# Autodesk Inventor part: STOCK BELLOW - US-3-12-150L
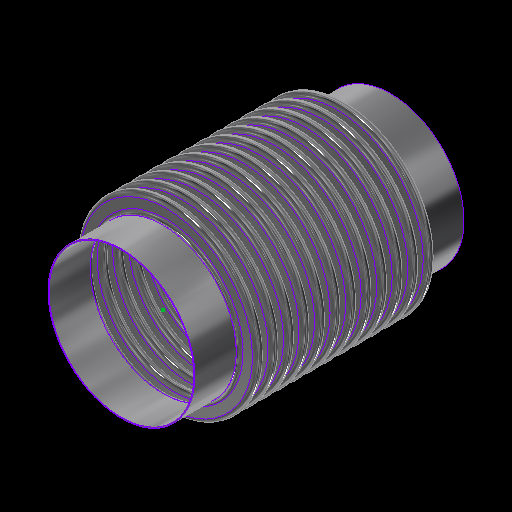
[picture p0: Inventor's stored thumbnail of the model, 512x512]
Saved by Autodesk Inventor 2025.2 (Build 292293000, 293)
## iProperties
Category: 24 GA (0.024 THICK)
RuleStatus: InUse
Created: 2024-01
Part Number: STOCK BELLOW - US-3-12-150L
Project: =STOCK BELLOWS: <Stock Number><SFILL>
Material: ASTM A240-304
Description: =STOCK BELLOWS: <Stock Number>, <SID_> I.D., <SOD_> O.D., <SPLY_> PLY, <Category>, <SNET_CONS> CONS.<PITCH_><STANGENT_> TANGENT<SFILL>
Document SubType Name: Sheet Metal
Designer: GS
Stock Number: U.S-3-12-150L
Surface Area: 2289.96 cm^2
Volume: 69.4846 cm^3
Sheet Metal Rule: Default
Appearance: STAINLESS STEEL
Mass: 559.857 g
Density: 8.05729 g/cm^3
THK: 0.036
ID: 3.500
OD: 4.250
CONS_: 2
PITCH: 0.500
TANGENT: 0.500
BELLOWS_UPSET: 0.000
d79: 1.000
d82: 1.000
d83: 26.000
d84: 24.000
d174: 8
d214: 8
STHK_: 0.024
SID_: 3.500
SOD_: 4.375
SPITCH_: 0.375
STANGENT__: 1.000
SBELLOWS_UPSET_: 0.000
SDIFF_TAN: 1.000
d252: 2
d275: 2
d287: 0.050
d289: 0.500
d290: 0.000
SOD_NECK: 3 9/16
PLY: 1
PSET: 4.178
PBAR: 1.035
COUNTER: 1.500
NET_TUBE: 3.071
CONS: 2
S_CONS: 0
NET_CONS: 2
ID_M: 88.90 mm
OD_M: 107.95 mm
THK_M: 0.91 mm
ID_U: 3.500 in
OD_U: 4.250 in
THK_U: 0.036 in
TANGENT2: 0.500
TAN_TO_TAN: 1.000 in
d80: 2.571
d81: 10
SID: 2.375
SCONS_: 12
SPITCH: 0.250
STANGENT_: 1.000
SBELLOWS_UPSET: 0.000
SNET_CONS: 12
SS_CONS: 0
SCONS: 8
d190: 8
d191: 1
d192: 1
d193: 8
d194: 0
SIZE: 3.00
PRESSURE: 150
d230: 8
STANGENT: 4.000
SPLY_: 1
d233: 8
d234: 0
d263: 2
d265: 1
d268: 2
d269: 0
d286: 2
d288: 1
d291: 2
d292: 0
SREROLL: 0.750
BLETP: 1.000 ul
PRES_Copy: 85
MATTABLE: 20 GA (0.036 THICK)
PART_NUMBER: U.S-3-12-150L
PITCH_: =, <SPITCH_> PITCH,
CFILL: .
SFILL: .
MESH: ,
COMP: 0.82
EXT: 0.41
LAT: 0.31
ANG: 573
ASR: 974
LSR: 1007
ANSR: 30
PRES: 150
COMPM: 8.2
EXTM: 4.1
LATM: 3.10
ASRM: 170.577
PRESM: 10.342
LSRM: 176.356
ANSRM: 5.254
TEMPMIN: 20
TEMPMAX: 800
TEMPMINM: -7
TEMPMAXM: 427
WEIGHTM: 0.560
WEIGHT: 1.234
Author: GS
Keywords: 20 GA (0.036 THICK)
Comments: =STOCK BELLOW - <STOCK NUMBER>
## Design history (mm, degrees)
sketch "Sketch2"
  geometry: L1 (0, -177.245)-(0, 562.856) reference; L2 (45.364, 0)-(44.45, 0); L3 (48.082, -2.718)-(50.343, -2.718); L4 (48.082, -3.632)-(50.343, -3.632); L5 (50.343, -9.982)-(48.082, -9.982); L6 (50.343, -9.068)-(48.082, -9.068); L7 (45.364, -12.7)-(44.45, -12.7); L8 (48.082, 0)-(48.082, -12.7); L9 (50.343, -6.35)-(53.975, -6.35); L10 (44.45, 0)-(44.45, -12.7); L11 (20.376, 102.841)-(20.376, 101.926); L12 (58.262, 457.127)-(58.262, 349.177); L13 (58.262, 444.427)-(58.262, 336.477); L14 (93.133, -58.817)-(93.133, -71.517); L15 (118.746, -66.401)-(118.746, -66.401); L16 (50.343, -9.068)-(50.343, -9.982); L17 (48.082, -9.068)-(48.082, -9.982); L18 (48.082, -9.525)-(50.343, -9.525); L19 (53.975, 0)-(53.975, -12.7); L20 (-50.343, -9.068)-(-50.343, -9.982); L21 (-50.343, -2.718)-(-48.082, -2.718); L22 (-50.343, -3.632)-(-48.082, -3.632); L23 (-48.082, -9.068)-(-50.343, -9.068); L24 (-50.343, -9.525)-(-48.082, -9.525); L25 (-48.082, -9.982)-(-50.343, -9.982); L26 (-48.082, -9.068)-(-48.082, -9.982); L27 (-44.45, 0.653)-(-44.45, -12.047); L28 (-48.082, -6.35)-(-44.45, -6.35); L29 (-50.343, 0.653)-(-50.343, -12.7); L30 (-53.061, 0)-(-53.975, 0); L31 (-53.975, 0)-(-53.975, -12.7); L32 (-53.061, -12.7)-(-53.975, -12.7); A1 r 2.718 centre (48.082, 0) between (45.364, 0) and (48.082, -2.718); A2 r 3.632 centre (48.082, 0) between (44.45, 0) and (48.082, -3.632); A3 r 3.632 centre (50.343, -6.35) between (50.343, -9.982) and (50.343, -2.718); A4 r 2.718 centre (50.343, -6.35) between (50.343, -9.068) and (50.343, -3.632); A5 r 2.718 centre (48.082, -12.7) between (48.082, -9.982) and (45.364, -12.7); A6 r 3.632 centre (48.082, -12.7) between (48.082, -9.068) and (44.45, -12.7); A7 r 3.175 centre (50.343, -6.35) between (50.343, -9.525) and (53.518, -6.35); A8 r 3.175 centre (48.082, -12.7) between (48.082, -9.525) and (44.907, -12.7); A9 r 2.718 centre (-50.343, -12.7) between (-50.343, -9.982) and (-53.061, -12.7); A10 r 2.718 centre (-48.082, -6.35) between (-48.082, -9.068) and (-48.082, -3.632); A11 r 3.175 centre (-48.082, -6.35) between (-48.082, -9.525) and (-44.907, -6.35); A12 r 3.632 centre (-48.082, -6.35) between (-48.082, -9.982) and (-48.082, -2.718); A13 r 3.175 centre (-50.343, -12.7) between (-50.343, -9.525) and (-53.518, -12.7); A14 r 3.632 centre (-50.343, -12.7) between (-50.343, -9.068) and (-53.975, -12.7); A15 r 2.718 centre (-50.343, 0) between (-53.061, 0) and (-50.343, -2.718); A16 r 3.632 centre (-50.343, 0) between (-53.975, 0) and (-50.343, -3.632); 10 further points
  constraints: 62 end point, 38 point on circle, 20 tangent, 16 centre point, 12 parallel, 9 midpoint, 7 vertical, 6 coincident, 6 concentric, 6 point on line, 4 equal radius, 4 perpendicular, 3 horizontal, 1 collinear, 1 horizontal alignment, 10 other
  dimensions: "THK" = 0.9144 distance of L11.start L11.end; "ID" = 88.9 distance of L11.end point (20.376, 13.026); "OD" = 107.95 distance of L12.start L12.end; "PITCH" = 12.7 distance of L12.start L13.start; "TANGENT" = 12.7 distance of L14.start L14.end; "BELLOWS_UPSET" = 0 distance of L15.start L15.end; "d43" = 88.9 diameter of L10 L1 (= ID); "d44" = 107.95 diameter of L9.end L1 (= OD); "d45" = 0.9144 distance between parallel lines of L5 L6 (computed from THK, PLY); "d46" = 3.6322 radius of A3 (computed from PITCH, THK, PLY); "UPSET_PITCH" = 12.7 distance of L2.end L7.end (derived); "SIDEWALL_ANGLE" = 360 deg dimension on L3 L9 (derived); "CON_GAP" = 5.4356 distance of point (48.082, -9.068) point (48.082, -3.632) (derived); "TAN1" = 4.98728 dimension on A8 (derived); "TAN2" = 4.98728 dimension on A7 (derived); "LEG1" = 2.2606 distance of L18.start L18.end (derived); "d278" = 0.9144 distance between parallel lines of L25 L23 (derived); "d279" = 3.6322 radius of A12 (derived); "d280" = 12.7 distance of L30.end L31.end (derived); "d281" = 360 deg dimension on L21 L28 (derived); "d282" = 5.4356 distance of point (-50.343, -9.068) point (-50.343, -3.632) (derived); "d283" = 4.98728 dimension on A13 (derived); "d284" = 4.98728 dimension on A11 (derived); "d285" = 2.2606 distance of L24.start L24.end (derived); "d293" = 88.9 diameter of L27 L1 (derived); "d294" = 107.95 diameter of L31 L1 (derived)
  node "Sketch Rectangular Pattern1" dims "d31" = 25.4, "ID" = 88.9
  node "Sketch Rectangular Pattern2" dims "d39" = 25.4, "PITCH" = 12.7
revolve "CONS" stored, may be unused: angle "d48" = 90 deg
node "BELLOW MIDPLANE"
pattern_linear "Rectangular Pattern2" dims "d52" = 12.7 (= UPSET_PITCH)
sketch "Sketch5"
  geometry: C1 r 45.364 at (0, 0) reference; C2 r 44.45 at (0, 0) reference
extrude "TANGENT" new body sketch "Sketch5" distance "d53" = 12.7 (= TANGENT); taper "d54" = 0 deg
revolve "SAMETAN" stored, may be unused: angle "d65" = 90 deg
revolve "DIFFTAN" stored, may be unused: angle "d70" = 90 deg
sketch "Sketch9"
  geometry: L1 (53.319, 0)-(-53.319, 0) reference; L2 (0, -17.78)-(0, 17.78) reference; L3 (38.085, 0)-(-38.085, 0); L4 (38.085, -11.906)-(38.085, 11.906); L5 (25.385, -11.906)-(25.385, 11.906); L6 (13.15, 11.906)-(13.15, -11.906); L7 (-25.385, -11.906)-(-25.385, 11.906); L8 (-38.085, -11.906)-(-38.085, 11.906); L9 (37.291, -11.906)-(37.291, 11.906); L10 (38.085, -11.906)-(37.291, -11.906); L11 (38.085, 11.906)-(37.291, 11.906); L12 (13.546, 11.906)-(12.753, 11.906); L13 (12.753, 11.906)-(12.753, -11.906); L14 (12.753, -11.906)-(13.546, -11.906); L15 (13.546, -11.906)-(13.546, 11.906); L16 (-13.546, 11.906)-(-13.546, -11.906); L17 (-13.15, 11.906)-(-13.15, -11.906); L18 (-13.546, -11.906)-(-12.753, -11.906); L19 (-12.753, -11.906)-(-12.753, 11.906); L20 (-12.753, 11.906)-(-13.546, 11.906); L21 (-38.085, -11.906)-(-37.291, -11.906); L22 (-37.291, -11.906)-(-37.291, 11.906); L23 (-37.291, 11.906)-(-38.085, 11.906); L24 (-38.085, 11.906)-(-38.085, -11.906); L25 (38.085, -0.397)-(-38.085, -0.397); L26 (-38.085, -0.397)-(-38.085, 0.397); L27 (-38.085, 0.397)-(38.085, 0.397); L28 (38.085, 0.397)-(38.085, -0.397); L29 (-38.085, 11.906)-(38.085, 11.906); L30 (38.085, 11.906)-(38.085, 12.7); L31 (38.085, 12.7)-(-38.085, 12.7); L32 (-38.085, 12.7)-(-38.085, 11.906); L33 (38.085, -11.906)-(-38.085, -11.906); L34 (-38.085, -11.906)-(-38.085, -12.7); L35 (-38.085, -12.7)-(38.085, -12.7); L36 (38.085, -12.7)-(38.085, -11.906); 30 further points
  constraints: 68 end point, 13 midpoint, 13 parallel, 8 horizontal, 7 perpendicular, 6 equal length, 3 point on line, 2 vertical, 14 other
  dimensions: "d115" = 23.8125 distance of L4.start L4.end (derived); "d116" = 12.7 distance between parallel lines of L4 L5 (derived); "d117" = 12.23516 distance between parallel lines of L5 L6 (derived); "d125" = 38.53427 distance between parallel lines of L7 L6 (derived); "d127" = 12.7 distance between parallel lines of L8 L7 (derived); "d128" = 24.93516 distance between parallel lines of L6 L4 (derived); "d130" = 76.16943 distance between parallel lines of L8 L4 (derived); "RULER_THK" = 0.79375 distance between parallel lines of L4 L9; "d135" = 0.79375 distance of L13.end L14.end (derived); "d138" = 26.29911 distance of L13.end L16.end (derived); "d143" = 0.79375 distance of L22.end L8.end (derived); "d144" = 0.79375 distance between parallel lines of L27 L25 (derived)
extrude "RULER" join sketch "Sketch9" distance "d149" = 0.79375 (derived); taper "d150" = 0 deg
extrude "BARS" join sketch "Sketch9" distance "d151" = 0.79375 (derived); taper "d152" = 0 deg
pattern_linear "Rectangular Pattern4" dims "d155" = 26.29911 (derived)
sketch "Sketch13"
  geometry: L1 (93.149, -52.467)-(93.149, -77.867); L2 (45.06, 0)-(44.45, 0); L3 (45.06, -9.525)-(44.45, -9.525); L4 (52.876, -7.449)-(47.136, -7.449); L5 (52.876, -6.839)-(47.136, -6.839); L6 (52.876, -4.762)-(55.562, -4.762); L7 (47.136, -2.076)-(52.876, -2.076); L8 (47.136, 0)-(47.136, -9.525); L9 (44.45, 0)-(44.45, -9.525); L10 (58.254, -385.306)-(58.254, -496.431); L11 (58.254, -394.831)-(58.254, -505.956); L12 (58.254, -413.881)-(58.254, -525.006); L13 (58.254, -423.406)-(58.254, -534.531); L14 (58.254, -432.931)-(58.254, -544.056); L15 (58.254, -442.456)-(58.254, -553.581); L16 (58.254, -451.981)-(58.254, -563.106); L17 (58.254, -404.356)-(58.254, -515.481); L18 (20.376, 102.536)-(20.376, 101.926); L19 (47.136, -2.686)-(52.876, -2.686); L20 (0, -696.234)-(0, 235.664) reference; L21 (-23.752, 0)-(142.514, 0) reference; A1 r 2.076 centre (47.136, 0) between (45.06, 0) and (47.136, -2.076); A2 r 2.076 centre (47.136, -9.525) between (47.136, -7.449) and (45.06, -9.525); A3 r 2.686 centre (47.136, -9.525) between (47.136, -6.839) and (44.45, -9.525); A4 r 2.076 centre (52.876, -4.762) between (52.876, -6.839) and (52.876, -2.686); A5 r 2.686 centre (52.876, -4.762) between (52.876, -7.449) and (52.876, -2.076); A6 r 2.686 centre (47.136, 0) between (44.45, 0) and (47.136, -2.686); 6 further points; 1 other entity
  constraints: 38 end point, 15 point on circle, 9 tangent, 6 centre point, 6 parallel, 5 vertical alignment, 4 point on line, 4 vertical, 3 coincident, 3 concentric, 2 collinear, 2 equal radius, 1 horizontal, 1 perpendicular, 23 other
  dimensions: "SBELLOWS_UPSET_" = 0 distance of point (118.762, -66.401) point (118.762, -66.401); "STOTAL_THK_BELLOW__" = 0.6096 distance between parallel lines of L4 L5 (derived); "d224" = 2.68605 radius of A5 (derived); "d225" = 9.525 distance of L2.end L3.end (derived); "SSIDEWALL_ANGLE_" = 0 deg angle of L7 L6 (derived); "SSCON_GAP_" = 4.1529 distance of point (47.136, -6.839) point (47.136, -2.686) (derived); "d235" = 88.9 diameter of L9 L20 (derived); "d236" = 111.125 diameter of L6.end L20 (derived)
  node "Sketch Rectangular Pattern4" dims "d228" = 25.4
  node "Sketch Rectangular Pattern5" dims "d229" = 25.4
revolve "SBELLOW" stored, may be unused: angle "d197" = 90 deg
pattern_linear "Rectangular Pattern5" dims "d204" = 9.525 (derived)
revolve "STANGENT" stored, may be unused: angle "d240" = 90 deg
revolve "SSAMETAN" stored, may be unused: angle "d241" = 90 deg
revolve "SDIFFTAN" stored, may be unused: angle "d246" = 90 deg
revolve "INVCON" stored, may be unused: angle "d295" = 90 deg
pattern_linear "Rectangular Pattern6" dims "d298" = 12.7 (derived)
revolve "INVTANGENT" stored, may be unused: angle "d302" = 90 deg
revolve "INVSAMETAN" stored, may be unused: angle "d307" = 90 deg
revolve "INVDIFFTAN" stored, may be unused: angle "d312" = 90 deg
sketch "ID BELLOW MOUNT CALC"
  geometry: L1 (44.45, 0)-(38.1, 0); L2 (38.1, 0)-(38.1, 12.7); L3 (38.1, 12.7)-(44.45, 12.7); L4 (44.45, 12.7)-(44.45, 0); L5 (36.513, 12.7)-(35.598, 12.7); L6 (35.598, 12.7)-(35.598, 0); L7 (35.598, 0)-(36.513, 0); L8 (36.513, 0)-(36.513, 12.7); L9 (0, -2.54)-(0, 15.24) reference; L10 (-8.89, 0)-(53.34, 0) reference; 1 further point
  constraints: 16 end point, 5 parallel, 2 collinear, 2 horizontal, 2 perpendicular
  dimensions: "d314" = 12.7 distance of L5.end L6.end (derived); "d315" = 0.9144 distance of L5.start L5.end (derived); "IG" = 1.5875 distance between parallel lines of L2 L8; "PIPE_OD" = 88.9 diameter of L4 L9; "PIPE_WALL" = 6.35 distance of L2.end L3.end; "ID_MT_BELLOW" = 71.1962 diameter of L6 L9 (derived)
revolve "CFILL" stored, may be unused: angle "d320" = 90 deg
pattern_linear "Rectangular Pattern7" dims "d323" = 12.7 (derived)
revolve "SFILL" stored, may be unused: angle "d324" = 90 deg
pattern_linear "Rectangular Pattern8" dims "d327" = 9.525 (derived)
node "STOCK BELLOW MIDPLANE"
node "BELLOW"
sketch "Sketch6"
  geometry: L1 (-12.7, 45.364)-(0, 45.364); L2 (0, 45.364)-(0, 44.45); L3 (0, 44.45)-(-12.7, 44.45); L4 (-12.7, 44.45)-(-12.7, 45.364); L5 (10.16, 0)-(-60.96, 0) reference; L6 (-38.1, -89.422)-(-38.1, 153.44) reference; 1 further point
  constraints: 8 end point, 2 parallel, 1 horizontal, 1 perpendicular
  dimensions: "d61" = 12.7 distance of L2.end L3.end (derived); "d62" = 0.9144 distance of L1.end L2.end (derived); "d63" = 88.9 diameter of L3 L5 (derived); "d64" = 25.4 distance between parallel lines of L4 L6 (derived)
sketch "Sketch12"
  geometry: 1 further point
sketch "Sketch14"
  geometry: L1 (-25.4, 45.06)-(0, 45.06); L2 (0, 45.06)-(0, 44.45); L3 (0, 44.45)-(-25.4, 44.45); L4 (-25.4, 44.45)-(-25.4, 45.06); L5 (5.08, 0)-(-30.48, 0) reference; L6 (0, -9.012)-(0, 54.072) reference; 1 further point
  constraints: 8 end point, 2 parallel, 1 collinear, 1 horizontal, 1 perpendicular
  dimensions: "d237" = 0.6096 distance of L3.end L1.start (derived); "d238" = 88.9 diameter of L3 L5 (derived); "d239" = 25.4 distance of L1.start L1.end (derived); "SOD_NECK" = 90.1192 diameter of L1 L5 (derived)
sketch "Sketch15"
  geometry: L1 (-9.012, 0)-(54.072, 0) reference; L2 (44.45, -114.3)-(45.06, -114.3); L3 (45.06, -114.3)-(45.06, -139.7); L4 (45.06, -139.7)-(44.45, -139.7); L5 (44.45, -139.7)-(44.45, -114.3); L6 (0, -170.18)-(0, 43.18) reference; 1 further point
  constraints: 8 end point, 2 parallel, 1 horizontal, 1 perpendicular
  dimensions: "d205" = 25.4 distance of L4.end L2.start (derived); "d206" = 0.6096 distance of L3.end L4.end (derived); "d207" = 88.9 diameter of L5 L6 (derived); "d208" = 114.3 distance between parallel lines of L1 L2 (derived)
node "TANGENT_"
node "SAME_TAN"
sketch "Sketch8"
  geometry: L1 (45.364, -25.4)-(44.45, -25.4); L2 (44.45, -25.4)-(44.45, -38.1); L3 (44.45, -38.1)-(45.364, -38.1); L4 (45.364, -38.1)-(45.364, -25.4); L5 (0, -48.26)-(0, 22.86) reference; L6 (-89.422, 0)-(153.44, 0) reference; 1 further point
  constraints: 8 end point, 2 parallel, 1 horizontal, 1 perpendicular
  dimensions: "d66" = 88.9 diameter of L2 L5 (derived); "TOTAL_THK_BELLOW" = 0.9144 distance of L2.end L3.end (derived); "d68" = 25.4 distance between parallel lines of L1 L6 (derived); "d69" = 12.7 distance of L1.end L2.end (derived)
node "DIFF_TAN"
node "Sketch Rectangular Pattern3" dims "d138" = 26.29911 (derived), "d141" = 25.4
node "SBELLOW_"
node "STANGENT_"
node "SSAME_TAN"
sketch "Sketch16"
  geometry: L1 (45.06, -114.3)-(44.45, -114.3); L2 (44.45, -114.3)-(44.45, -139.7); L3 (44.45, -139.7)-(45.06, -139.7); L4 (45.06, -139.7)-(45.06, -114.3); L5 (0, -170.18)-(0, 43.18) reference; L6 (-9.012, 0)-(54.072, 0) reference; 1 further point
  constraints: 8 end point, 2 parallel, 1 horizontal, 1 perpendicular
  dimensions: "SDIFF_TAN" = 25.4 distance of L3.end L1.start; "d243" = 0.6096 distance of L2.end L3.end (derived); "d244" = 114.3 distance between parallel lines of L1 L6 (derived); "d245" = 88.9 diameter of L2 L5 (derived)
node "SDIFF_TAN"
body "Solid15"
sketch "Sketch17"
  geometry: L1 (53.975, 12.7)-(53.061, 12.7); L2 (53.061, 12.7)-(53.061, 0); L3 (53.061, 0)-(53.975, 0); L4 (53.975, 0)-(53.975, 12.7); L5 (0, -2.54)-(0, 15.24) reference; L6 (-10.795, 0)-(64.77, 0) reference; 2 further points
  constraints: 8 end point, 2 parallel, 1 horizontal, 1 midpoint, 1 perpendicular, 1 point on line
  dimensions: "INVTANGENT" = 12.7 distance of L3.end L1.start (derived); "d300" = 0.9144 distance of L1.start L1.end (derived); "d301" = 107.95 diameter of L4 L5 (derived)
body "Solid16"
sketch "Sketch18"
  geometry: L1 (53.975, -25.4)-(53.061, -25.4); L2 (53.061, -25.4)-(53.061, -38.1); L3 (53.061, -38.1)-(53.975, -38.1); L4 (53.975, -38.1)-(53.975, -25.4); L5 (-10.795, 0)-(64.77, 0) reference; L6 (0, -48.26)-(0, 22.86) reference; 1 further point
  constraints: 8 end point, 2 parallel, 1 horizontal, 1 perpendicular
  dimensions: "d303" = 25.4 distance between parallel lines of L1 L5 (derived); "d304" = 12.7 distance of L3.end L1.start (derived); "d305" = 0.9144 distance of L2.end L3.end (derived); "d306" = 107.95 diameter of L4 L6 (derived)
body "Solid17"
sketch "Sketch19"
  geometry: L1 (53.975, -25.4)-(53.061, -25.4); L2 (53.061, -25.4)-(53.061, -38.1); L3 (53.061, -38.1)-(53.975, -38.1); L4 (53.975, -38.1)-(53.975, -25.4); L5 (0, -48.26)-(0, 22.86) reference; L6 (-10.795, 0)-(64.77, 0) reference; 1 further point
  constraints: 8 end point, 2 parallel, 1 horizontal, 1 perpendicular
  dimensions: "d308" = 12.7 distance of L1.end L2.end (derived); "d309" = 107.95 diameter of L4 L5 (derived); "d310" = 0.9144 distance of L2.end L3.end (derived); "d311" = 25.4 distance between parallel lines of L1 L6 (derived)
body "Solid18"
body "Solid19"
body "Solid20"
other parameters: "BMPL" = -57.15, "PSET" = 106.1212 (computed from OD, THK, PLY) [user parameter], "PBAR" = 26.29911 (= 0.570796 x PITCH + OD - ID) [user parameter; used in 1 equation term], "COUNTER" = 15 [user parameter], "NET_TUBE" = 77.99823 (computed from CONS_, PBAR, TANGENT) [user parameter], "S_CONS" = 0 [user parameter; used in 1 equation term], "ID_M" = 88.9 (= ID) [user parameter], "OD_M" = 107.95 (= OD) [user parameter], "THK_M" = 0.9144 (= THK) [user parameter], "ID_U" = 88.9 (= ID) [user parameter], "OD_U" = 107.95 (= OD) [user parameter], "THK_U" = 0.9144 (= THK) [user parameter], "D_UNITS" = 0 [user parameter], "TANGENT2" = 12.7 [user parameter], "TAN_TO_TAN" = 25.4 [user parameter], "OD_NECK" = 90.7288 [user parameter], "d79" = 25.4, "d80" = 65.29823 [user parameter], "d82" = 25.4, "d83" = 660.4, "d84" = 609.6, "sa_0" = 4, "FRAME_THK" = 0.79375 [user parameter], "CON_FLAT" = 12.23516 [user parameter], "SID" = 60.325 [user parameter], "SPITCH" = 6.35 [user parameter], "STANGENT_" = 25.4 [user parameter], "SBELLOWS_UPSET" = 0 [user parameter], "SS_CONS" = 0 [user parameter], "STAN_TO_TAN_" = 114.3 [user parameter], "d100" = 0.6096 [user parameter], "d191" = 25.4 [user parameter], "d194" = 0 [user parameter], "STANGENT" = 101.6 [user parameter], "d234" = 0 [user parameter], "SUPSET_PITCH_" = 9.525 [user parameter], "d269" = 0 [user parameter], "d287" = 1.27, "d289" = 12.7, "d290" = 0, "d292" = 0 [user parameter], "Thickness" = 3.048 (derived), "KFactor" = 4.4, "BendRadius" = 3.048 (derived), "BendReliefWidth" = 3.048 (derived), "BendReliefDepth" = 1.524 (derived), "CornerReliefSize" = 12.192 (derived), "SeamGap" = 0.00508, "MinimumRemnant" = 6.096 (derived), "TransitionRadius" = 3.048 (derived), "JacobiRadiusSize" = 3.048 (derived), "GapSize" = 3.048 (derived), "SREROLL" = 19.05 [user parameter], "CUR_STK_PITCH" = 9.525 [user parameter], "d328" = -57.15 (derived), "LSR" = 10070 [user parameter], "BLETP" = 1 [user parameter], "ASRM" = 1705.7662 [user parameter], "PRESM" = 103.41975 [user parameter], "LSRM" = 1763.5591 [user parameter], "ANSRM" = 52.539 [user parameter], "TEMPMIN" = 2664.83333 [user parameter], "TEMPMAX" = 6998.16667 [user parameter], "TEMPMINM" = 2664.83333 [user parameter], "TEMPMAXM" = 6998.16667 [user parameter], "WEIGHT" = 5.59857 [user parameter], "WEIGHTM" = 0.0056 [user parameter]
